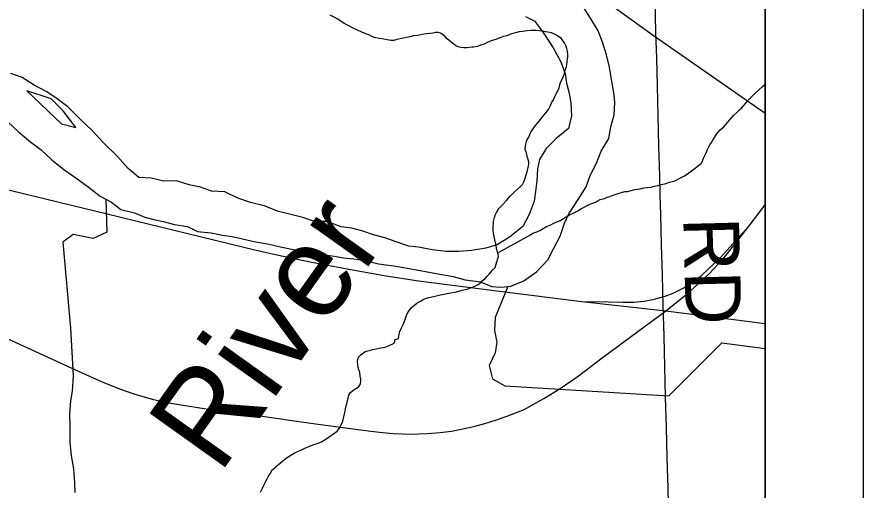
# Model space of a CAD drawing. Extents: x -6.1 to 38, y -7.7 to 22.
# Drawn here: x 8.136 to 9, y 18.449 to 18.932 of the extents above; entities that cross this region are included whole.
import ezdxf

# ---------------------------------------------------------------- set-up
doc = ezdxf.new("R2010")
doc.units = 0
for name, color, linetype in [('GM_X_Corporation', 7, 'Continuous'), ('GM_X_Major_River', 7, 'Continuous'), ('GM_X_Minor_River', 7, 'Continuous'), ('GM_X_Minor_River_Text', 7, 'Continuous'), ('GM_X_Rail_Line', 7, 'Continuous'), ('GM_X_Township_Road', 7, 'Continuous'), ('GM_X_Township_Road_Text', 7, 'Continuous'), ('SH_Data', 7, 'Continuous')]:
    doc.layers.add(name, color=color, linetype=linetype)

msp = doc.modelspace()

# ---------------------------------------------------------------- linework, layer by layer
at = {"layer": 'GM_X_Corporation'}
for points in [[(8.9, 14.85918), (8.9, 19.87135), (8.53815, 19.88018), (8.02661, 19.88922), (8.02125, 19.70471), (8.02079, 19.68982), (8.0189, 19.62846), (7.99279, 18.77986), (7.97287, 17.92154), (7.97183, 17.87641), (7.95308, 17.06692), (7.95307, 17.06643), (7.93594, 16.3267), (7.92512, 16.10977), (7.91657, 15.91251), (7.90988, 15.74002), (7.90533, 15.62285), (7.88899, 15.0865), (7.88923, 14.89059), (8.1023, 14.88375), (8.27757, 14.87811), (8.6137, 14.86789)], [(8.9, 14.68725), (8.9, 19.53649), (8.77571, 19.53237), (8.77312, 19.53228), (6.99327, 19.47331), (6.99349, 19.46054), (7.03821, 16.8882), (7.05054, 16.17866), (7.07262, 15.21743), (7.07601, 15.03919), (7.07603, 15.03845), (7.07902, 14.88093), (7.08348, 14.64684), (7.55487, 14.65733), (8.5875, 14.68029)]]:
    msp.add_lwpolyline(points, close=True, dxfattribs=at)
at = {"layer": 'GM_X_Major_River'}
for points in [[(8.36639, 18.70524), (8.37964, 18.70224), (8.39363, 18.69963), (8.40499, 18.69701), (8.41672, 18.69476), (8.44207, 18.6899), (8.46022, 18.68768), (8.46931, 18.68581), (8.4799, 18.6847), (8.49314, 18.68284), (8.50525, 18.67984), (8.52076, 18.67761), (8.53286, 18.67575), (8.54384, 18.6735), (8.55859, 18.67089), (8.56768, 18.66902), (8.58129, 18.66678), (8.59378, 18.66341), (8.60929, 18.66118), (8.62068, 18.6567), (8.63051, 18.656), (8.64034, 18.65683), (8.65354, 18.66222), (8.66634, 18.6714), (8.67798, 18.68361), (8.68433, 18.69579), (8.69068, 18.70796), (8.69514, 18.72126), (8.69961, 18.73077), (8.70897, 18.74524), (8.71721, 18.75819), (8.72129, 18.76997), (8.72764, 18.78253), (8.73247, 18.79469), (8.74033, 18.80764), (8.74252, 18.81941), (8.74585, 18.83194), (8.74652, 18.84484), (8.74532, 18.85469), (8.74297, 18.86795), (8.74099, 18.88046), (8.73789, 18.89295), (8.73402, 18.90582), (8.72941, 18.91755), (8.72176, 18.93039), (8.71374, 18.94286)], [(8.65519, 18.93225), (8.66468, 18.92738), (8.67536, 18.91265), (8.68339, 18.90019), (8.69104, 18.88659), (8.69566, 18.8741), (8.69723, 18.86425), (8.69995, 18.85403), (8.70152, 18.84418), (8.70236, 18.83091), (8.69904, 18.81799), (8.68663, 18.80767), (8.67649, 18.79737), (8.66938, 18.78633), (8.66755, 18.77684), (8.66687, 18.76432), (8.66543, 18.75369), (8.66398, 18.74382), (8.65915, 18.73014), (8.65242, 18.71796), (8.63888, 18.70688), (8.62645, 18.69921), (8.61475, 18.69572), (8.60002, 18.69336), (8.58717, 18.69214), (8.57431, 18.69244), (8.55993, 18.69386), (8.54593, 18.69681), (8.53608, 18.69789), (8.52207, 18.70235), (8.51145, 18.70607), (8.50009, 18.70942), (8.48796, 18.71351), (8.47773, 18.7161), (8.46714, 18.71755), (8.45273, 18.72277), (8.43987, 18.72307), (8.42775, 18.72716), (8.41563, 18.73012), (8.40313, 18.73308), (8.38834, 18.73905), (8.37433, 18.74238), (8.36144, 18.74685), (8.34817, 18.75321), (8.33455, 18.75389), (8.32318, 18.75799), (8.31182, 18.76019), (8.29894, 18.76428), (8.28567, 18.76416), (8.2728, 18.76716), (8.26034, 18.76784), (8.24932, 18.77687), (8.23865, 18.78932), (8.22419, 18.80326), (8.21277, 18.8157), (8.20021, 18.82776), (8.18803, 18.83982), (8.17549, 18.84922), (8.16562, 18.85561), (8.15348, 18.86198), (8.14132, 18.86987), (8.12957, 18.87396)], [(8.14589, 18.85631), (8.18146, 18.82259), (8.19588, 18.81896)], [(8.19588, 18.81896), (8.1832, 18.83588), (8.17095, 18.84825), (8.14589, 18.85631)], [(8.12649, 18.82465), (8.13753, 18.81448), (8.14969, 18.80431), (8.16071, 18.79604), (8.17136, 18.78586), (8.18391, 18.77608), (8.19606, 18.76743), (8.2086, 18.75841), (8.22076, 18.74863), (8.23253, 18.74263), (8.24203, 18.73511), (8.25589, 18.73185), (8.2665, 18.72733), (8.27558, 18.72508), (8.28522, 18.72286), (8.29696, 18.7199), (8.31021, 18.71771), (8.32045, 18.71284), (8.33423, 18.71122), (8.34596, 18.70897), (8.3558, 18.70749), (8.36639, 18.70524)]]:
    msp.add_lwpolyline(points, dxfattribs=at)
at = {"layer": 'GM_X_Minor_River'}
for points in [[(8.68632, 18.91335), (8.68403, 18.91445), (8.68173, 18.91555), (8.67792, 18.91624), (8.67525, 18.91658), (8.67296, 18.91729), (8.66954, 18.91761), (8.66573, 18.91793), (8.66118, 18.91785), (8.65663, 18.91738), (8.65246, 18.91693), (8.64867, 18.91648), (8.64489, 18.91565), (8.64111, 18.91444), (8.63621, 18.91245), (8.6328, 18.91163), (8.62903, 18.91042), (8.62488, 18.90883), (8.6211, 18.90762), (8.61695, 18.90603), (8.61319, 18.90406), (8.60941, 18.90285), (8.6064, 18.90165), (8.6045, 18.90124), (8.60223, 18.90082), (8.60034, 18.90078), (8.59807, 18.90037), (8.59541, 18.90032), (8.59237, 18.90026), (8.58932, 18.90059), (8.58665, 18.9013), (8.58397, 18.90239), (8.57742, 18.9076), (8.57511, 18.90946), (8.57317, 18.91171), (8.57048, 18.91394), (8.56856, 18.91504), (8.56589, 18.91576), (8.56323, 18.91571), (8.56058, 18.91528), (8.55754, 18.91485), (8.55451, 18.91441), (8.55148, 18.91398), (8.54845, 18.91354), (8.54543, 18.91273), (8.54088, 18.91227), (8.5371, 18.91144), (8.53369, 18.91062), (8.53066, 18.91018), (8.52726, 18.90936), (8.52386, 18.90854), (8.52083, 18.90772), (8.51818, 18.90768), (8.51589, 18.90802), (8.51361, 18.90836), (8.51055, 18.90906), (8.50598, 18.90974), (8.50255, 18.91044), (8.49912, 18.91152), (8.49605, 18.91299), (8.49223, 18.91444), (8.48802, 18.91626), (8.48381, 18.91809), (8.47921, 18.92029), (8.47499, 18.9225), (8.47078, 18.9247), (8.46694, 18.92691), (8.46347, 18.92951), (8.45925, 18.93172), (8.4558, 18.93356)], [(8.55065, 18.64322), (8.55328, 18.64441), (8.55669, 18.64523), (8.56122, 18.64645), (8.56841, 18.64811), (8.57711, 18.64978), (8.58469, 18.65106), (8.59073, 18.65269), (8.59603, 18.65392), (8.59905, 18.65512), (8.60206, 18.65631), (8.6047, 18.6575), (8.60696, 18.65868), (8.60884, 18.65986), (8.61107, 18.66218), (8.61369, 18.66451), (8.61593, 18.66683), (8.61854, 18.66954), (8.62113, 18.67301), (8.62412, 18.6761), (8.62591, 18.68184), (8.62699, 18.68528), (8.62772, 18.68719), (8.6273, 18.68908), (8.62689, 18.69098), (8.62607, 18.69401), (8.62525, 18.69779), (8.62482, 18.70045), (8.6244, 18.70234), (8.62399, 18.70424), (8.62317, 18.70765), (8.62274, 18.71068), (8.62231, 18.71333), (8.62227, 18.71561), (8.62222, 18.71827), (8.62255, 18.72094), (8.62252, 18.72284), (8.62358, 18.72704), (8.6243, 18.72934), (8.62577, 18.73203), (8.62797, 18.73625), (8.63208, 18.74013), (8.6358, 18.74438), (8.63953, 18.74862), (8.64363, 18.75288), (8.64736, 18.75637), (8.65035, 18.75909), (8.65222, 18.76064), (8.65369, 18.76333), (8.65441, 18.766), (8.65549, 18.76944), (8.65693, 18.77365), (8.65763, 18.77671), (8.65834, 18.77938), (8.65868, 18.78167), (8.65864, 18.78395), (8.65743, 18.78811), (8.65661, 18.79114), (8.6558, 18.79417), (8.655, 18.79643), (8.65532, 18.79948), (8.65566, 18.80177), (8.65638, 18.80444), (8.65709, 18.80674), (8.65857, 18.80905), (8.65966, 18.81173), (8.66076, 18.81403), (8.66224, 18.81634), (8.66372, 18.81864), (8.66557, 18.82096), (8.66743, 18.82327), (8.6693, 18.82521), (8.67189, 18.82868), (8.67412, 18.83138), (8.67635, 18.83408), (8.67857, 18.83716), (8.68041, 18.84062), (8.68187, 18.84407), (8.68372, 18.84714), (8.68517, 18.85059), (8.68664, 18.85328), (8.68811, 18.85635), (8.68957, 18.85941), (8.69064, 18.86362), (8.69465, 18.87281), (8.69536, 18.87549), (8.69607, 18.87816), (8.69716, 18.88084), (8.69749, 18.88351), (8.69783, 18.8858), (8.69817, 18.88847), (8.6985, 18.89114), (8.69845, 18.8938), (8.69802, 18.89683), (8.69759, 18.89949), (8.6964, 18.90251), (8.69521, 18.90515), (8.69365, 18.90702), (8.6917, 18.91003), (8.68824, 18.91225), (8.68632, 18.91335)], [(8.62689, 18.69098), (8.66036, 18.70945), (8.66261, 18.71101), (8.66677, 18.71223), (8.66978, 18.7138), (8.67316, 18.71576), (8.67654, 18.71773), (8.68031, 18.71932), (8.68407, 18.72128), (8.68784, 18.72287), (8.69086, 18.72407), (8.69349, 18.72564), (8.69687, 18.7276), (8.70026, 18.72956), (8.70402, 18.73153), (8.70666, 18.73272), (8.70929, 18.73428), (8.71192, 18.73585), (8.7202, 18.74019), (8.72208, 18.74098), (8.72397, 18.74177), (8.72661, 18.74258), (8.72849, 18.74376), (8.7315, 18.74533), (8.73603, 18.74655), (8.73867, 18.74774), (8.74131, 18.74855), (8.74471, 18.74975), (8.74773, 18.75094), (8.75075, 18.75176), (8.7534, 18.75257), (8.7568, 18.75339), (8.75946, 18.75344), (8.76323, 18.75464), (8.76702, 18.75547), (8.76967, 18.7559), (8.77232, 18.75633), (8.7761, 18.75716), (8.77989, 18.7576), (8.7833, 18.75804), (8.78709, 18.75887), (8.79087, 18.7597), (8.79427, 18.76052), (8.79843, 18.76174), (8.8022, 18.76295), (8.80523, 18.76376), (8.80787, 18.76457), (8.81051, 18.76576), (8.81352, 18.76733), (8.8169, 18.76929), (8.82066, 18.77164), (8.82478, 18.77476), (8.82853, 18.77749), (8.8319, 18.78021), (8.83452, 18.78216), (8.836, 18.78447), (8.83708, 18.78753), (8.83965, 18.7929), (8.84111, 18.79635), (8.84257, 18.79904), (8.84367, 18.80133), (8.84515, 18.80364), (8.84663, 18.80595), (8.8481, 18.80864), (8.85032, 18.8121), (8.85404, 18.81635), (8.85778, 18.81946), (8.86783, 18.83105), (8.87119, 18.83415), (8.8738, 18.83686), (8.87604, 18.8388), (8.87753, 18.84073), (8.87976, 18.84343), (8.88273, 18.8469), (8.88647, 18.8504), (8.88983, 18.85388), (8.89319, 18.85698), (8.8973, 18.86086), (8.89991, 18.86318), (8.9, 18.86326)], [(8.22675, 18.74558), (8.22759, 18.71206), (8.21362, 18.70558), (8.20341, 18.70745), (8.19319, 18.7097), (8.18263, 18.70171), (8.19045, 18.61416), (8.19325, 18.56526), (8.19216, 18.54971), (8.19068, 18.53985), (8.18958, 18.52658), (8.19, 18.51369), (8.19005, 18.49777), (8.19123, 18.48375), (8.19354, 18.47049), (8.19472, 18.45608), (8.19512, 18.44623)], [(8.63736, 18.65658), (8.62415, 18.62482), (8.62343, 18.61155), (8.62612, 18.59981), (8.62426, 18.58881), (8.61825, 18.5759), (8.62169, 18.56227), (8.63419, 18.5551), (8.80175, 18.54496), (8.85566, 18.59895), (8.9, 18.59341)], [(8.38478, 18.4467), (8.38661, 18.45054), (8.38844, 18.45437), (8.3899, 18.45782), (8.39174, 18.4609), (8.39321, 18.46358), (8.3947, 18.46551), (8.39615, 18.46896), (8.39952, 18.47168), (8.40176, 18.474), (8.40476, 18.47634), (8.40737, 18.47867), (8.41037, 18.481), (8.413, 18.48257), (8.41562, 18.48452), (8.41901, 18.48648), (8.4224, 18.48806), (8.42579, 18.48965), (8.42918, 18.49122), (8.43408, 18.49322), (8.43823, 18.49481), (8.44238, 18.49641), (8.44691, 18.49801), (8.45142, 18.50075), (8.46304, 18.50894), (8.46526, 18.51203), (8.4671, 18.51548), (8.46856, 18.51893), (8.46962, 18.52351), (8.47032, 18.52657), (8.47103, 18.52924), (8.47137, 18.53153), (8.47207, 18.53496), (8.4728, 18.53688), (8.47349, 18.54031), (8.47421, 18.54261), (8.47492, 18.54566), (8.47639, 18.54835), (8.47901, 18.5503), (8.48088, 18.55185), (8.48277, 18.55265), (8.48501, 18.55459), (8.48686, 18.55728), (8.48719, 18.55995), (8.48716, 18.56185), (8.48635, 18.56488), (8.4859, 18.56867), (8.48509, 18.57132), (8.48428, 18.57397), (8.48386, 18.57662), (8.48379, 18.58004), (8.48414, 18.58195), (8.48486, 18.58425), (8.48709, 18.58695), (8.48971, 18.5889), (8.49159, 18.59007), (8.49423, 18.59088), (8.49726, 18.59169), (8.49915, 18.59211), (8.50104, 18.59252), (8.50748, 18.59378), (8.50975, 18.5942), (8.51202, 18.59462), (8.51541, 18.59582), (8.51729, 18.597), (8.51918, 18.59779), (8.52143, 18.59897), (8.52213, 18.6024), (8.52553, 18.60361), (8.52655, 18.61009), (8.52876, 18.61431), (8.53021, 18.61776), (8.53167, 18.62121), (8.53276, 18.62389), (8.53385, 18.62695), (8.5353, 18.63078), (8.53716, 18.63271), (8.53865, 18.63464), (8.54425, 18.63969), (8.54651, 18.64087), (8.54877, 18.64205), (8.55065, 18.64322)]]:
    msp.add_lwpolyline(points, dxfattribs=at)
at = {"layer": 'GM_X_Rail_Line'}
for points in [[(6.19287, 19.69813), (6.21792, 19.65768), (6.25419, 19.613), (6.2935, 19.58374), (6.34004, 19.56589), (6.38312, 19.55199), (6.4273, 19.55367), (6.48418, 19.56365), (6.64401, 19.60019), (6.71957, 19.61741), (6.76764, 19.62675), (6.84656, 19.6383), (7.43863, 19.63931), (7.50222, 19.63795), (7.56146, 19.62521), (7.63701, 19.60108), (7.88712, 19.52077), (7.95726, 19.49994), (8.00695, 19.47618), (8.05679, 19.43987), (8.28809, 19.27109), (8.78458, 18.9138), (8.9, 18.83346)], [(7.86069, 18.81984), (8.22816, 18.73065), (8.37877, 18.694), (8.40136, 18.68882), (8.43717, 18.68145), (8.47499, 18.67409), (8.5108, 18.6679), (8.54611, 18.66238), (8.62877, 18.65183), (8.71294, 18.64129), (8.79869, 18.63161), (8.9, 18.61895)], [(8.12588, 18.60344), (8.20025, 18.56931), (8.22298, 18.55929), (8.24074, 18.55221), (8.2554, 18.54699), (8.27389, 18.5417), (8.29051, 18.53779), (8.34215, 18.52948), (8.37921, 18.52533), (8.44063, 18.51653), (8.49725, 18.50904), (8.5093, 18.50757), (8.52054, 18.50651), (8.5383, 18.50586), (8.55492, 18.50635), (8.56803, 18.50741), (8.57984, 18.50887), (8.59125, 18.51115), (8.60241, 18.51368), (8.61373, 18.51669), (8.62562, 18.52052), (8.63719, 18.52451), (8.64615, 18.52785), (8.65397, 18.53103), (8.67409, 18.54227), (8.69079, 18.55253), (8.70789, 18.56451), (8.73477, 18.58471), (8.79869, 18.63161), (8.8205, 18.64913), (8.84244, 18.66903), (8.857, 18.68468), (8.87068, 18.70165), (8.88369, 18.71832), (8.9, 18.73985)], [(8.71294, 18.64129), (8.73961, 18.64079), (8.75467, 18.64043), (8.76601, 18.64065), (8.77632, 18.64167), (8.78656, 18.64365), (8.79702, 18.64643), (8.80616, 18.64972), (8.8164, 18.65498), (8.82577, 18.66105), (8.83491, 18.66786), (8.85451, 18.68622), (8.88369, 18.71832)]]:
    msp.add_lwpolyline(points, dxfattribs=at)
at = {"layer": 'GM_X_Township_Road'}
msp.add_lwpolyline([(8.80168, 18.41952), (8.80085, 18.45057), (8.80002, 18.48163), (8.7992, 18.51269), (8.79837, 18.54374), (8.79754, 18.5748), (8.79672, 18.60585), (8.79589, 18.63691), (8.79506, 18.66797), (8.79424, 18.69902), (8.79341, 18.73008), (8.79289, 18.7494), (8.79237, 18.76873), (8.79157, 18.79978), (8.79076, 18.83084), (8.78995, 18.8619), (8.78924, 18.88928), (8.78852, 18.91667), (8.78776, 18.94772)], dxfattribs=at)
at = {"layer": 'SH_Data'}
for p, q in [((9, 21), (9, 14)), ((8.9, 20.9), (8.9, 14.1))]:
    msp.add_line(p, q, dxfattribs=at)

# ---------------------------------------------------------------- texts
at = {"layer": 'GM_X_Minor_River_Text'}
msp.add_text('River', height=0.094764, rotation=54.49708, dxfattribs=at).set_placement((8.3425, 18.4636))
at = {"layer": 'GM_X_Township_Road_Text'}
msp.add_text('RD', height=0.056818, rotation=271.45472, dxfattribs=at).set_placement((8.81635, 18.72663))

doc.saveas('drawing.dxf')
